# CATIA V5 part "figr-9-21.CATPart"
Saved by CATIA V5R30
Part number: Part3
Bounding box of the stored display mesh (mm): x -112 to 0, y -101.683 to 104.654, z -80.304 to 44.557
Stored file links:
  D:\PROJECTS\CATIA V56R 2020\Resources\Parts File\c09_catia_v5_6r2020_prt\figr-9-21.CATPart
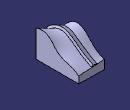
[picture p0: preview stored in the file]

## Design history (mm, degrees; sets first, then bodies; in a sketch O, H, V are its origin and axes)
Set1
  Plane1: type Offset, RefPlane yz-plane, Offset -112
  Plane2: type Offset, RefPlane yz-plane, Offset -63
  Plane3: type Normal, Curve Sketch4, RefPoint vertex of Sketch4
Body1 (main body)
  Sketch1 on yz-plane, origin (0, 0, 0), H (0, 1, 0), V (0, 0, 1)
    spline S1 through (-92.6897, 40.1119) (-30, 30) (10, -10) (60, -30) (97.3103, -50.3041)
    line L1 (97.3103, -50.3041) -> (97.3103, -80.3041)
    line L2 (97.3103, -80.3041) -> (-92.6897, -80.3041)
    line L3 (-92.6897, -80.3041) -> (-92.6897, 40.1119)
    point P3 (-92.6897, 40.1119)
    point P4 (97.3103, -50.3041)
    point P5 (-92.6897, 40.1119)
    point P6 (97.3103, -50.3041)
    vertical: L1 V, L3 V
    horizontal: L2 H
    coincidence: P5 P3, P6 P4
  Sketch2 on Plane1, origin (-112, 0, 0), H (0, 1, 0), V (0, 0, 1)
    spline S1 through (-90, -30) (-70, 10) (-20, 40) (40, 0) (100, -40)
    line L1 (100, -40) -> (100, -80)
    line L2 (100, -80) -> (-90, -80)
    line L3 (-90, -80) -> (-90, -30)
    point P3 (-90, -30)
    point P4 (100, -40)
    point P5 (40, 0)
    point P6 (-90, -30)
    point P7 (100, -40)
    coincidence: P5 H, P6 P3, P7 P4
    vertical: L1 V, L3 V
    horizontal: L2 H
  Loft1: Sections (Sketch1; Sketch2)
  Sketch3 on Plane3, origin (0, -40.1726, -44.9298), H (1, 0, 0), V (0, -0.7455, 0.6665)
    point P1 (-63, 68.4187)
    line L1 (-63, 68.4187) -> (-75.2117, 62.4925)
    line L2 (-75.2117, 62.4925) -> (-79.6266, 71.5898)
    line L3 (-79.6266, 71.5898) -> (-57.1205, 82.5119)
    line L4 (-57.1205, 82.5119) -> (-52.7056, 73.4145)
    point P5 (-52.7056, 73.4145)
    line L5 (-52.7056, 73.4145) -> (-63, 68.4187)
    reference projected point E1 (-63, 68.4187) from vertex of Sketch4
    perpendicularity: L2 L1
    parallelism: L3 L1, L4 L2, L5 L1
    coincidence: P5 L1, P1 E1
  Sketch4 on Plane2, origin (-63, 0, 0), H (0, 1, 0), V (0, 0, 1)
    intersected curve E1 from face of Loft1
  Rib1: profile Sketch3, centre curve Sketch4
